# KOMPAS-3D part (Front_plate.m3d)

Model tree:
1. X Axis
2. Y Axis
3. Z Axis
4. Origin  (labels: D:\Program Files\ASCON\KOMPAS-3D V10\Sys\GRAPHIC_EN.LYT; Plate 03)
     Wall Thickness 1 = 1; Wall Thickness 2 = 1; Distance 1 = 10; Distance 2 = 10

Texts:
  Plate 03
  Three Point Plane
  Plane at Angle
  Line and Point Plane
  Axis through Two Vertices
  Axis of Feature
  Axis of Conical Surface
  Axis through Edge
  Trim by Surface
  Trim by Sketch
  Feature with No History
  Intersection Axis of Two Planes
  Two Line Plane
  Line and Face Plane
  Bend by line
  Hole in sheet body
  Cut in sheet body
  Point in CM
  Linear Dimension from Line to Point
  Surface Finish Symbol
  Geometric Tolerance Symbol
  Leader #1
  Leader #2
  Leader #3
  Shape Deviations and Datum
  Node point number
  Mark of coordination axis
  Node point designation
  Mark/Reference designation with leader
  Mark/reference designation on line
  Mark/Reference designation without leader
